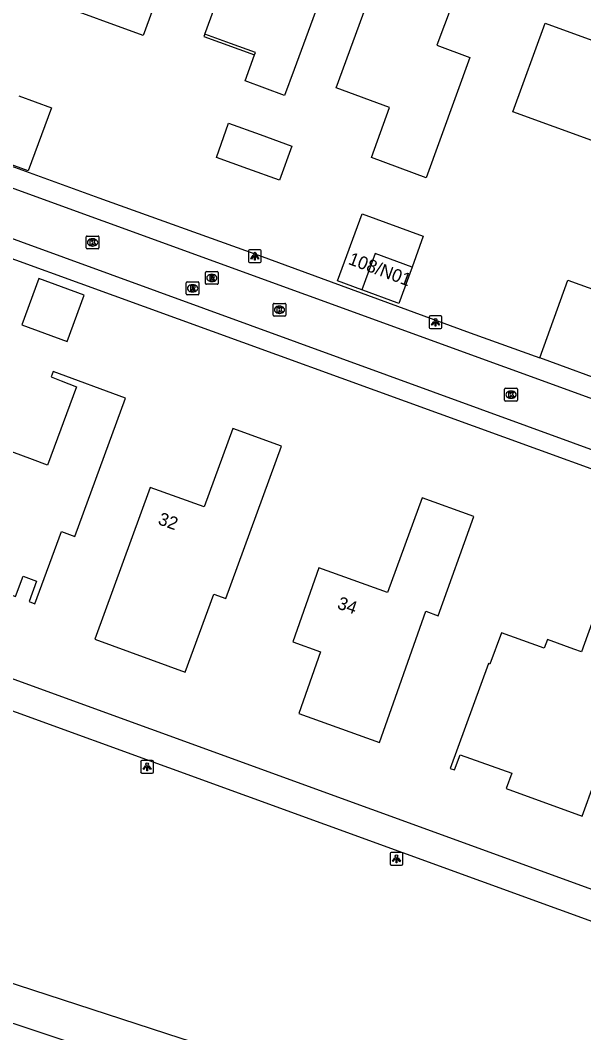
# Model space of a CAD drawing. Extents: x 155275 to 156263, y 382654 to 383635.
# Drawn here: x 155908.2 to 155952.1, y 382832.2 to 382911.2 of the extents above; entities that cross this region are included whole.
import ezdxf

# ---------------------------------------------------------------- set-up
doc = ezdxf.new("R2010")
doc.units = 0
for name, color, linetype in [('IMGEO_Kolk', 7, 'Continuous'), ('IMGEO_Lichtpunt', 7, 'Continuous'), ('IMGEO_Loofbos', 7, 'Continuous'), ('IMGEO_Pand', 7, 'Continuous'), ('IMGEO_Pand_nummerreeks', 7, 'Continuous'), ('IMGEO_Pand_overbouw', 7, 'Continuous'), ('IMGEO_Rijbaan_lokaal_gesloten', 7, 'Continuous'), ('IMGEO_Rijbaan_lokaal_open', 7, 'Continuous'), ('IMGEO_Rioolput', 7, 'Continuous'), ('IMGEO_Voetpad_open', 7, 'Continuous')]:
    doc.layers.add(name, color=color, linetype=linetype)

msp = doc.modelspace()

# ---------------------------------------------------------------- linework, layer by layer
at = {"layer": 'IMGEO_Kolk'}
for p, q in [((155913.286, 382893.413), (155913.286, 382894.265)), ((155913.361, 382894.339), (155914.213, 382894.339)), ((155913.774, 382894.119), (155913.799, 382894.119)), ((155914.287, 382894.265), (155914.287, 382893.413)), ((155914.213, 382893.339), (155913.361, 382893.339)), ((155913.797, 382893.559), (155913.772, 382893.559)), ((155927.858, 382888.164), (155927.858, 382889.016)), ((155927.933, 382889.09), (155928.785, 382889.09)), ((155928.859, 382889.016), (155928.859, 382888.164)), ((155928.369, 382888.31), (155928.344, 382888.31)), ((155928.346, 382888.87), (155928.371, 382888.87)), ((155928.785, 382888.09), (155927.933, 382888.09)), ((155945.904, 382881.543), (155945.904, 382882.395)), ((155945.979, 382882.469), (155946.831, 382882.469)), ((155946.392, 382882.249), (155946.417, 382882.249)), ((155946.905, 382882.395), (155946.905, 382881.543)), ((155946.831, 382881.469), (155945.979, 382881.469)), ((155946.415, 382881.689), (155946.39, 382881.689))]:
    msp.add_line(p, q, dxfattribs=at)
for points in [[(155913.286, 382893.413), (155913.286, 382894.265)], [(155913.361, 382894.339), (155914.213, 382894.339)], [(155913.607, 382894.039), (155913.73, 382894.039), (155913.73, 382893.888), (155913.86, 382894.039), (155914.024, 382894.039), (155913.878, 382893.888), (155914.031, 382893.639), (155913.879, 382893.639), (155913.794, 382893.803), (155913.73, 382893.736), (155913.73, 382893.639), (155913.607, 382893.639), (155913.607, 382894.039)], [(155914.287, 382894.265), (155914.287, 382893.413)], [(155914.213, 382893.339), (155913.361, 382893.339)], [(155927.858, 382888.164), (155927.858, 382889.016)], [(155927.933, 382889.09), (155928.785, 382889.09)], [(155928.859, 382889.016), (155928.859, 382888.164)], [(155928.179, 382888.79), (155928.302, 382888.79), (155928.302, 382888.639), (155928.432, 382888.79), (155928.596, 382888.79), (155928.45, 382888.639), (155928.603, 382888.39), (155928.451, 382888.39), (155928.366, 382888.554), (155928.302, 382888.487), (155928.302, 382888.39), (155928.179, 382888.39), (155928.179, 382888.79)], [(155928.785, 382888.09), (155927.933, 382888.09)], [(155945.904, 382881.543), (155945.904, 382882.395)], [(155945.979, 382882.469), (155946.831, 382882.469)], [(155946.225, 382882.169), (155946.348, 382882.169), (155946.348, 382882.018), (155946.478, 382882.169), (155946.642, 382882.169), (155946.496, 382882.018), (155946.649, 382881.769), (155946.497, 382881.769), (155946.412, 382881.933), (155946.348, 382881.866), (155946.348, 382881.769), (155946.225, 382881.769), (155946.225, 382882.169)], [(155946.905, 382882.395), (155946.905, 382881.543)], [(155946.831, 382881.469), (155945.979, 382881.469)]]:
    msp.add_lwpolyline(points, dxfattribs=at)
for centre, start, end in [((155913.363, 382894.263), 91.55205, 178.44795), ((155913.363, 382894.263), 91.55205, 178.44795), ((155914.211, 382894.263), 1.55205, 88.44795), ((155914.211, 382894.263), 1.55205, 88.44795), ((155913.363, 382893.415), 181.55205, 268.44795), ((155913.363, 382893.415), 181.55205, 268.44795), ((155914.211, 382893.415), 271.55205, 358.44795), ((155914.211, 382893.415), 271.55205, 358.44795), ((155927.935, 382889.014), 91.55205, 178.44795), ((155927.935, 382889.014), 91.55205, 178.44795), ((155928.783, 382889.014), 1.55205, 88.44795), ((155928.783, 382889.014), 1.55205, 88.44795), ((155927.935, 382888.166), 181.55205, 268.44795), ((155927.935, 382888.166), 181.55205, 268.44795), ((155928.783, 382888.166), 271.55205, 358.44795), ((155928.783, 382888.166), 271.55205, 358.44795), ((155945.981, 382882.393), 91.55205, 178.44795), ((155945.981, 382882.393), 91.55205, 178.44795), ((155946.829, 382882.393), 1.55205, 88.44795), ((155946.829, 382882.393), 1.55205, 88.44795), ((155945.981, 382881.545), 181.55205, 268.44795), ((155945.981, 382881.545), 181.55205, 268.44795), ((155946.829, 382881.545), 271.55205, 358.44795), ((155946.829, 382881.545), 271.55205, 358.44795)]:
    msp.add_arc(centre, 0.0765, start, end, dxfattribs=at)
for centre, major_axis, ratio, start_param, end_param in [((155913.773, 382893.839), (-0.387, 0.002), 0.722429, 4.712389, 7.853982), ((155913.798, 382893.839), (-0.39, 0.002), 0.717154, 1.570796, 4.712389), ((155928.345, 382888.59), (-0.387, 0.002), 0.722429, 4.712389, 7.853982), ((155928.37, 382888.59), (-0.39, 0.002), 0.717154, 1.570796, 4.712389), ((155946.391, 382881.969), (-0.387, 0.002), 0.722429, 4.712389, 7.853982), ((155946.416, 382881.969), (-0.39, 0.002), 0.717154, 1.570796, 4.712389)]:
    msp.add_ellipse(centre, major_axis=major_axis, ratio=ratio, start_param=start_param, end_param=end_param, dxfattribs=at)
at = {"layer": 'IMGEO_Lichtpunt'}
for p, q in [((155925.938, 382893.173), (155925.938, 382892.366)), ((155925.938, 382893.173), (155925.938, 382892.366)), ((155926.84, 382893.268), (155926.032, 382893.268)), ((155926.84, 382893.268), (155926.032, 382893.268)), ((155926.934, 382892.366), (155926.934, 382893.173)), ((155926.934, 382892.366), (155926.934, 382893.173)), ((155926.032, 382892.272), (155926.84, 382892.272)), ((155926.032, 382892.272), (155926.84, 382892.272)), ((155940.021, 382888.021), (155940.021, 382887.214)), ((155940.021, 382888.021), (155940.021, 382887.214)), ((155940.923, 382888.116), (155940.115, 382888.116)), ((155940.923, 382888.116), (155940.115, 382888.116)), ((155941.017, 382887.214), (155941.017, 382888.021)), ((155941.017, 382887.214), (155941.017, 382888.021)), ((155940.115, 382887.12), (155940.923, 382887.12)), ((155940.115, 382887.12), (155940.923, 382887.12)), ((155918.44, 382853.459), (155917.632, 382853.459)), ((155918.44, 382853.459), (155917.632, 382853.459)), ((155917.538, 382853.364), (155917.538, 382852.557)), ((155917.538, 382853.364), (155917.538, 382852.557)), ((155918.534, 382852.557), (155918.534, 382853.364)), ((155918.534, 382852.557), (155918.534, 382853.364)), ((155917.632, 382852.463), (155918.44, 382852.463)), ((155917.632, 382852.463), (155918.44, 382852.463)), ((155936.971, 382846.19), (155936.971, 382845.383)), ((155936.971, 382846.19), (155936.971, 382845.383)), ((155937.873, 382846.285), (155937.065, 382846.285)), ((155937.873, 382846.285), (155937.065, 382846.285)), ((155937.967, 382845.383), (155937.967, 382846.19)), ((155937.967, 382845.383), (155937.967, 382846.19)), ((155937.065, 382845.289), (155937.873, 382845.289)), ((155937.065, 382845.289), (155937.873, 382845.289))]:
    msp.add_line(p, q, dxfattribs=at)
for points in [[(155926.312, 382892.837), (155926.351, 382892.809), (155926.163, 382892.547), (155926.125, 382892.574), (155926.312, 382892.837)], [(155926.414, 382892.789), (155926.461, 382892.789), (155926.461, 382892.467), (155926.414, 382892.467), (155926.414, 382892.789)], [(155926.524, 382892.809), (155926.562, 382892.836), (155926.749, 382892.574), (155926.71, 382892.546), (155926.524, 382892.809)], [(155940.395, 382887.685), (155940.434, 382887.657), (155940.246, 382887.395), (155940.208, 382887.422), (155940.395, 382887.685)], [(155940.497, 382887.637), (155940.544, 382887.637), (155940.544, 382887.315), (155940.497, 382887.315), (155940.497, 382887.637)], [(155940.607, 382887.657), (155940.645, 382887.684), (155940.832, 382887.422), (155940.793, 382887.394), (155940.607, 382887.657)], [(155917.912, 382853.028), (155917.951, 382853), (155917.763, 382852.738), (155917.725, 382852.765), (155917.912, 382853.028)], [(155918.014, 382852.98), (155918.061, 382852.98), (155918.061, 382852.658), (155918.014, 382852.658), (155918.014, 382852.98)], [(155918.124, 382853), (155918.162, 382853.027), (155918.349, 382852.765), (155918.31, 382852.737), (155918.124, 382853)], [(155937.345, 382845.854), (155937.384, 382845.826), (155937.196, 382845.564), (155937.158, 382845.591), (155937.345, 382845.854)], [(155937.447, 382845.806), (155937.494, 382845.806), (155937.494, 382845.484), (155937.447, 382845.484), (155937.447, 382845.806)], [(155937.557, 382845.826), (155937.595, 382845.853), (155937.782, 382845.591), (155937.743, 382845.563), (155937.557, 382845.826)]]:
    msp.add_lwpolyline(points, dxfattribs=at)
for centre in [(155926.437, 382892.971), (155940.52, 382887.819), (155918.037, 382853.162), (155937.47, 382845.988)]:
    msp.add_circle(centre, 0.0994, dxfattribs=at)
for centre, start, end in [((155926.032, 382893.173), 90, 180), ((155926.032, 382893.173), 90, 180), ((155926.84, 382893.173), 0, 90), ((155926.84, 382893.173), 0, 90), ((155926.032, 382892.366), 180, 270), ((155926.032, 382892.366), 180, 270), ((155926.84, 382892.366), 270, 0), ((155926.84, 382892.366), 270, 360), ((155940.115, 382888.021), 90, 180), ((155940.115, 382888.021), 90, 180), ((155940.923, 382888.021), 0, 90), ((155940.923, 382888.021), 0, 90), ((155940.115, 382887.214), 180, 270), ((155940.115, 382887.214), 180, 270), ((155940.923, 382887.214), 270, 0), ((155940.923, 382887.214), 270, 360), ((155917.632, 382853.364), 90, 180), ((155917.632, 382853.364), 90, 180), ((155918.44, 382853.364), 0, 90), ((155918.44, 382853.364), 0, 90), ((155917.632, 382852.557), 180, 270), ((155917.632, 382852.557), 180, 270), ((155918.44, 382852.557), 270, 0), ((155918.44, 382852.557), 270, 360), ((155937.065, 382846.19), 90, 180), ((155937.065, 382846.19), 90, 180), ((155937.873, 382846.19), 0, 90), ((155937.873, 382846.19), 0, 90), ((155937.065, 382845.383), 180, 270), ((155937.065, 382845.383), 180, 270), ((155937.873, 382845.383), 270, 0), ((155937.873, 382845.383), 270, 360)]:
    msp.add_arc(centre, 0.0946, start, end, dxfattribs=at)
at = {"layer": 'IMGEO_Loofbos'}
msp.add_lwpolyline([(155937.541, 382826.332), (155936.958, 382826.589), (155920.684, 382831.77), (155660.436, 382916.637), (155650.027, 382919.992), (155641.261, 382922.57), (155632.466, 382925.283), (155625.045, 382928.281)], dxfattribs=at)
at = {"layer": 'IMGEO_Pand'}
for points in [[(155914.647, 382923.261), (155919.9, 382921.373), (155918.663, 382917.977), (155918.513, 382917.567), (155920.266, 382916.925), (155917.723, 382909.978), (155910.732, 382912.528)], [(155928.756, 382905.303), (155925.671, 382906.434), (155926.415, 382908.456), (155926.48, 382908.635), (155924.544, 382909.342), (155922.541, 382910.074), (155925.258, 382917.543), (155925.913, 382919.269), (155929.253, 382918.067), (155932.945, 382916.739), (155929.498, 382907.325), (155928.756, 382905.303)], [(155935.522, 382900.474), (155936.94, 382904.362), (155932.781, 382905.886), (155936.452, 382915.97), (155942.334, 382913.78), (155940.631, 382909.207), (155943.19, 382908.254), (155939.798, 382898.882), (155935.522, 382900.474)], [(155946.532, 382904.015), (155949.068, 382910.933), (155952.992, 382909.515), (155953.114, 382909.847), (155955.905, 382908.822), (155955.571, 382907.883), (155958.568, 382906.802), (155958.616, 382906.785), (155961.447, 382905.762), (155959.155, 382899.44), (155946.532, 382904.015)], [(155908.04, 382905.267), (155910.579, 382904.343), (155908.774, 382899.418), (155906.245, 382900.34)], [(155928.358, 382898.683), (155925.89, 382899.573), (155923.442, 382900.456), (155924.393, 382903.138), (155926.857, 382902.246), (155929.322, 382901.354), (155928.358, 382898.683)], [(155934.769, 382890.147), (155932.891, 382890.842), (155934.811, 382896.076), (155939.567, 382894.317), (155938.69, 382891.924)], [(155938.69, 382891.924), (155935.809, 382892.981), (155934.769, 382890.147)], [(155938.69, 382891.924), (155937.648, 382889.083), (155937.525, 382889.128), (155934.85, 382890.118), (155934.769, 382890.147)], [(155913.138, 382889.728), (155909.591, 382891.016), (155908.266, 382887.424), (155911.806, 382886.118), (155913.138, 382889.728)], [(155948.645, 382884.835), (155950.836, 382890.892), (155956.798, 382888.735), (155954.606, 382882.673)], [(155954.606, 382882.673), (155948.645, 382884.835)], [(155916.368, 382881.708), (155910.729, 382883.785), (155910.564, 382883.369), (155911.35, 382883.058), (155912.533, 382882.59), (155910.279, 382876.467), (155909.113, 382876.916), (155904.45, 382878.63), (155902.669, 382873.75), (155903.157, 382873.569), (155901.331, 382868.599), (155907.789, 382866.226), (155908.371, 382867.813), (155909.423, 382867.426), (155908.84, 382865.84), (155909.3, 382865.671), (155911.369, 382871.303), (155912.411, 382870.92), (155916.368, 382881.708)], [(155928.505, 382877.966), (155924.724, 382879.341), (155922.499, 382873.227), (155918.282, 382874.744), (155913.97, 382862.913), (155921.016, 382860.344), (155923.242, 382866.419), (155924.182, 382866.077), (155928.505, 382877.966)], [(155943.508, 382872.485), (155939.467, 382873.936), (155936.788, 382866.56), (155931.426, 382868.459), (155929.386, 382862.7), (155931.564, 382861.929), (155929.858, 382857.112), (155936.147, 382854.859), (155939.758, 382865.087), (155940.727, 382864.739), (155943.508, 382872.485)], [(155960.615, 382869.359), (155959.896, 382869.617), (155959.447, 382868.397), (155954.863, 382870.042), (155954.61, 382869.334), (155954.019, 382869.55), (155953.391, 382867.922), (155953.964, 382867.686), (155951.902, 382861.924), (155951.304, 382862.133), (155949.248, 382862.887), (155948.995, 382862.202), (155945.669, 382863.398), (155944.755, 382860.959), (155944.638, 382861.01), (155941.666, 382852.832), (155941.995, 382852.714), (155942.44, 382853.904), (155946.456, 382852.459), (155946.026, 382851.264), (155951.937, 382849.119), (155952.902, 382851.767), (155954.069, 382851.347), (155960.615, 382869.359)]]:
    msp.add_lwpolyline(points, dxfattribs=at)
at = {"layer": 'IMGEO_Pand_overbouw'}
msp.add_lwpolyline([(155926.415, 382908.456), (155926.48, 382908.635), (155924.544, 382909.342), (155922.541, 382910.074), (155922.473, 382909.885)], close=True, dxfattribs=at)
at = {"layer": 'IMGEO_Rijbaan_lokaal_gesloten'}
msp.add_lwpolyline([(155642.872, 382919.148), (155649.107, 382917.137), (155659.516, 382913.782), (155681.378, 382906.655), (155707.492, 382898.143), (155734, 382889.508), (155762.271, 382880.46), (155792.38, 382870.456), (155818.814, 382861.879), (155845.361, 382853.249), (155875.166, 382843.61), (155900.261, 382835.383), (155919.774, 382828.911), (155936.048, 382823.73)], dxfattribs=at)
at = {"layer": 'IMGEO_Rijbaan_lokaal_open'}
for points in [[(155880.59, 382907.807), (155883.262, 382906.894), (155961.679, 382878.39)], [(155879.327, 382904.418), (155961.883, 382874.346)]]:
    msp.add_lwpolyline(points, dxfattribs=at)
at = {"layer": 'IMGEO_Rioolput'}
for p, q in [((155922.583, 382890.649), (155922.583, 382891.501)), ((155922.658, 382891.575), (155923.51, 382891.575)), ((155923.071, 382891.355), (155923.096, 382891.355)), ((155923.584, 382891.501), (155923.584, 382890.649)), ((155921.08, 382889.836), (155921.08, 382890.688)), ((155921.155, 382890.762), (155922.007, 382890.762)), ((155921.568, 382890.542), (155921.593, 382890.542)), ((155922.081, 382890.688), (155922.081, 382889.836)), ((155923.51, 382890.575), (155922.658, 382890.575)), ((155923.094, 382890.795), (155923.069, 382890.795)), ((155922.007, 382889.762), (155921.155, 382889.762)), ((155921.591, 382889.982), (155921.566, 382889.982))]:
    msp.add_line(p, q, dxfattribs=at)
for points in [[(155922.583, 382890.649), (155922.583, 382891.501)], [(155922.658, 382891.575), (155923.51, 382891.575)], [(155923.584, 382891.501), (155923.584, 382890.649)], [(155921.08, 382889.836), (155921.08, 382890.688)], [(155921.155, 382890.762), (155922.007, 382890.762)], [(155922.081, 382890.688), (155922.081, 382889.836)], [(155923.51, 382890.575), (155922.658, 382890.575)], [(155923.172, 382891.273), (155922.92, 382891.275), (155922.92, 382890.875)], [(155922.92, 382890.875), (155923.044, 382890.875), (155923.044, 382891.037), (155923.055, 382891.037)], [(155923.098, 382891.194), (155923.044, 382891.194), (155923.044, 382891.113)], [(155923.044, 382891.113), (155923.096, 382891.113)], [(155923.102, 382891.008), (155923.173, 382890.875), (155923.313, 382890.875), (155923.248, 382891.001)], [(155922.007, 382889.762), (155921.155, 382889.762)], [(155921.669, 382890.46), (155921.417, 382890.462), (155921.417, 382890.062)], [(155921.417, 382890.062), (155921.541, 382890.062), (155921.541, 382890.224), (155921.552, 382890.224)], [(155921.595, 382890.381), (155921.541, 382890.381), (155921.541, 382890.3)], [(155921.541, 382890.3), (155921.593, 382890.3)], [(155921.599, 382890.195), (155921.67, 382890.062), (155921.81, 382890.062), (155921.745, 382890.188)]]:
    msp.add_lwpolyline(points, dxfattribs=at)
for centre, radius, start, end in [((155922.66, 382891.499), 0.0765, 91.55205, 178.44795), ((155922.66, 382891.499), 0.0765, 91.55205, 178.44795), ((155923.508, 382891.499), 0.0765, 1.55205, 88.44795), ((155923.508, 382891.499), 0.0765, 1.55205, 88.44795), ((155921.157, 382890.686), 0.0765, 91.55205, 178.44795), ((155921.157, 382890.686), 0.0765, 91.55205, 178.44795), ((155922.005, 382890.686), 0.0765, 1.55205, 88.44795), ((155922.005, 382890.686), 0.0765, 1.55205, 88.44795), ((155922.66, 382890.651), 0.0765, 181.55205, 268.44795), ((155922.66, 382890.651), 0.0765, 181.55205, 268.44795), ((155923.054, 382890.984), 0.0533, 26.02933, 88.69889), ((155923.08, 382891.302), 0.19, 274.7715, 282.96867), ((155923.104, 382891.098), 0.0964, 77.00612, 93.18647), ((155923.118, 382891.155), 0.0378, 276.66336, 79.67722), ((155923.171, 382891.163), 0.109, 350.36119, 89.41601), ((155923.169, 382891.163), 0.112, 277.58423, 350.98172), ((155923.153, 382890.948), 0.108, 29.51342, 73.79051), ((155923.508, 382890.651), 0.0765, 271.55205, 358.44795), ((155923.508, 382890.651), 0.0765, 271.55205, 358.44795), ((155921.157, 382889.838), 0.0765, 181.55205, 268.44795), ((155921.157, 382889.838), 0.0765, 181.55205, 268.44795), ((155921.551, 382890.171), 0.0533, 26.02933, 88.69889), ((155921.577, 382890.489), 0.19, 274.7715, 282.96867), ((155921.601, 382890.285), 0.0964, 77.00612, 93.18647), ((155921.615, 382890.342), 0.0378, 276.66336, 79.67722), ((155921.668, 382890.35), 0.109, 350.36119, 89.41601), ((155921.666, 382890.35), 0.112, 277.58423, 350.98172), ((155921.65, 382890.135), 0.108, 29.51342, 73.79051), ((155922.005, 382889.838), 0.0765, 271.55205, 358.44795), ((155922.005, 382889.838), 0.0765, 271.55205, 358.44795)]:
    msp.add_arc(centre, radius, start, end, dxfattribs=at)
for centre, major_axis, ratio, start_param, end_param in [((155923.07, 382891.075), (-0.387, 0.002), 0.722429, 4.712389, 7.853982), ((155923.095, 382891.075), (-0.39, 0.002), 0.717154, 1.570796, 4.712389), ((155921.567, 382890.262), (-0.387, 0.002), 0.722429, 4.712389, 7.853982), ((155921.592, 382890.262), (-0.39, 0.002), 0.717154, 1.570796, 4.712389)]:
    msp.add_ellipse(centre, major_axis=major_axis, ratio=ratio, start_param=start_param, end_param=end_param, dxfattribs=at)
at = {"layer": 'IMGEO_Voetpad_open'}
for points in [[(155882.198, 382908.814), (155888.809, 382906.56), (155914.272, 382897.319), (155926.717, 382892.835), (155943.231, 382886.789), (155948.645, 382884.835)], [(155879.75, 382902.636), (155961.133, 382873.112)], [(155953.058, 382843.257), (155866.062, 382874.889)], [(155962.277, 382837.428), (155865.28, 382872.649), (155863.949, 382873.132)]]:
    msp.add_lwpolyline(points, dxfattribs=at)

# ---------------------------------------------------------------- texts
at = {"layer": 'IMGEO_Pand_nummerreeks'}
for s, rotation, p in [('108/N01', 339.49384, (155933.649, 382892.174)), ('32', 340.2146, (155918.821, 382871.893)), ('34', 340.49795, (155932.785, 382865.325))]:
    msp.add_text(s, height=1, rotation=rotation, dxfattribs=at).set_placement(p)

doc.saveas('drawing.dxf')
